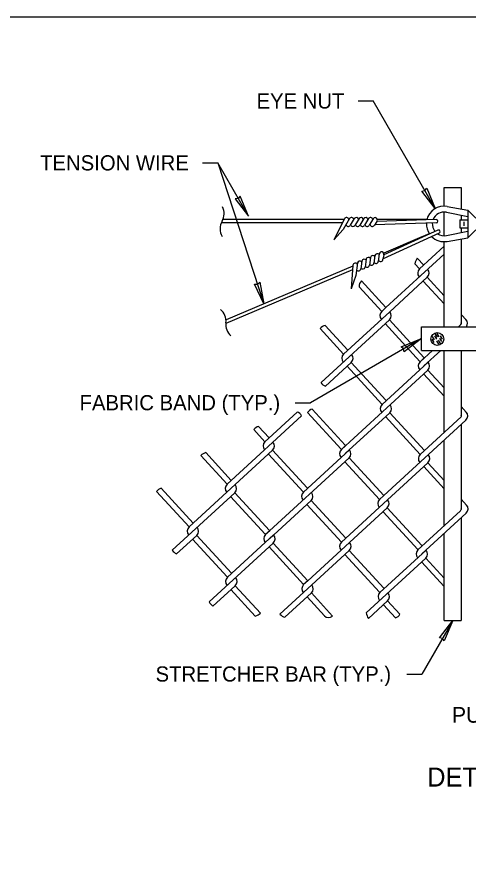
# Model space of a CAD drawing. Extents: x 99862 to 104211, y 98939 to 105076.
# Drawn here: x 101442 to 101919, y 104179 to 105076 of the extents above; entities that cross this region are included whole.
import ezdxf

# ---------------------------------------------------------------- set-up
doc = ezdxf.new("R2010")
doc.units = 0
for name, color, linetype in [('Level 1', 7, 'Continuous'), ('Level 15', 7, 'Continuous'), ('Level 2', 7, 'Continuous'), ('Level 20', 7, 'Continuous'), ('Level 4', 7, 'Continuous'), ('Level 7', 7, 'Continuous')]:
    doc.layers.add(name, color=color, linetype=linetype)

msp = doc.modelspace()

# ---------------------------------------------------------------- linework, layer by layer
at = {"layer": 'Level 1'}
msp.add_lwpolyline([(99862, 102999.5), (103151, 102999.5), (103151, 105075.5), (99862, 105075.5)], close=True, dxfattribs=at)
at = {"layer": 'Level 15'}
for p, q in [((101801.93, 104987.03), (101817.93, 104987.03)), ((101883.35, 104873.71), (101817.93, 104987.03)), ((101637.88, 104921.79), (101653.88, 104921.79)), ((101686.38, 104865.5), (101653.88, 104921.79)), ((101653.88, 104921.79), (101702.72, 104773.36)), ((101868.71, 104736.56), (101751.71, 104669.01)), ((101735.71, 104669.01), (101751.71, 104669.01)), ((101901.78, 104439.37), (101869.28, 104383.07)), ((101853.28, 104383.07), (101869.28, 104383.07))]:
    msp.add_line(p, q, dxfattribs=at)
for points in [[(101883.35, 104873.71), (101869.35, 104891.99), (101872.46, 104892.57), (101874.52, 104894.98)], [(101686.38, 104865.5), (101677.55, 104886.77), (101675.5, 104884.36), (101672.38, 104883.78)], [(101702.72, 104773.36), (101692.75, 104794.11), (101695.91, 104794.04), (101698.42, 104795.98)], [(101868.71, 104736.56), (101850.43, 104722.56), (101849.86, 104725.67), (101847.45, 104727.73)], [(101901.78, 104439.37), (101892.95, 104418.1), (101890.9, 104420.51), (101887.78, 104421.09)]]:
    msp.add_lwpolyline(points, close=True, dxfattribs=at)
at = {"layer": 'Level 2'}
for p, q in [((101896.01, 104875.93), (101917.63, 104872.08)), ((101917.63, 104872.08), (101926.05, 104863.66)), ((101917.63, 104872.08), (101917.63, 104842.88)), ((101787.51, 104862.78), (101776.31, 104840.57)), ((101792.9, 104863.08), (101786.2, 104851.62)), ((101797.96, 104863.17), (101793.76, 104856.09)), ((101802.99, 104863.21), (101798.54, 104855.75)), ((101807.94, 104863.14), (101803.75, 104856.03)), ((101812.87, 104863.05), (101808.75, 104855.96)), ((101817.82, 104862.97), (101813.83, 104856.05)), ((101895.11, 104869.75), (101917.63, 104865.37)), ((101785.33, 104858.47), (101657.69, 104858.47)), ((101787.1, 104861.97), (101659.44, 104861.97)), ((101821.83, 104860.01), (101819.14, 104856.18)), ((101884.43, 104858.52), (101819.39, 104856.53)), ((101884.28, 104861.92), (101821.83, 104860.02)), ((101863.33, 104861.93), (101822.43, 104861.93)), ((101874.51, 104861.93), (101863.33, 104861.93)), ((101909.39, 104861.65), (101909.39, 104853.31)), ((101909.39, 104861.65), (101917.63, 104861.65)), ((101913.55, 104859.56), (101913.55, 104855.4)), ((101786.2, 104851.62), (101776.31, 104840.57)), ((101887.39, 104847.76), (101828.27, 104820.58)), ((101885.93, 104850.83), (101829.16, 104824.75)), ((101877.11, 104847.11), (101866.64, 104842.68)), ((101895.14, 104845.22), (101917.63, 104849.65)), ((101909.39, 104853.31), (101917.63, 104853.31)), ((101917.63, 104842.88), (101926.05, 104851.3)), ((101866.64, 104842.68), (101828.97, 104826.74)), ((101896.01, 104839.03), (101917.63, 104842.88)), ((101805.95, 104818.34), (101804.85, 104810.18)), ((101810.57, 104820.34), (101809.37, 104811.74)), ((101815.15, 104822.21), (101814.06, 104814.03)), ((101819.73, 104824.04), (101818.7, 104815.91)), ((101824.32, 104825.9), (101823.33, 104817.97)), ((101829.17, 104824.74), (101828.18, 104820.17)), ((101796.15, 104809.1), (101662.54, 104752.56)), ((101796.41, 104813.01), (101662.7, 104756.43)), ((101796.47, 104813.91), (101794.82, 104789.09)), ((101801.32, 104816.29), (101799.62, 104803.12)), ((101799.62, 104803.12), (101794.82, 104789.09))]:
    msp.add_line(p, q, dxfattribs=at)
msp.add_circle((101885.54, 104736.08), 6.76, dxfattribs=at)
for centre, radius, start, end in [((101644.72, 104868.22), 15.99, 330, 26.99342), ((101892.72, 104857.48), 18.75, 79.88873, 167.22506), ((101789.74, 104861.65), 2.5, 6.40357, 153.24227), ((101794.95, 104861.65), 2.5, 12.67704, 145.12641), ((101799.95, 104861.65), 2.5, 12.59822, 142.68795), ((101804.95, 104861.65), 2.5, 12.71791, 141.47087), ((101809.95, 104861.65), 2.5, 12.8499, 143.37719), ((101814.95, 104861.65), 2.5, 12.90749, 146.13672), ((101819.95, 104861.65), 2.5, 318.96056, 148.1098), ((101892.72, 104857.48), 12.5, 78.97929, 159.15425), ((101672.42, 104852.23), 15.99, 150, 210), ((101791.6, 104857.36), 2.5, 194.6987, 329.36298), ((101796.58, 104857.31), 2.5, 193.30049, 321.47087), ((101801.58, 104857.31), 2.5, 192.67765, 329.47272), ((101806.65, 104857.31), 2.5, 191.7767, 327.41573), ((101811.65, 104857.31), 2.5, 192.8499, 329.97706), ((101816.91, 104857.31), 2.5, 185.27391, 333.22218), ((101892.72, 104857.48), 18.75, 177.80235, 214.51032), ((101892.72, 104857.48), 12.5, 175.82468, 219.51772), ((101884.43, 104860.22), 1.71, 270, 90), ((101892.72, 104857.48), 12.5, 236.61904, 281.13621), ((101886.73, 104849.33), 1.71, 292.93564, 112.93564), ((101892.72, 104857.48), 18.75, 225.33181, 280.11127), ((101826.79, 104825.51), 2.5, 341.89619, 171.04544), ((101803.77, 104815.77), 2.5, 35.61267, 168.06204), ((101808.37, 104817.72), 2.5, 35.53386, 165.62358), ((101812.98, 104819.67), 2.5, 35.65354, 164.40651), ((101817.58, 104821.62), 2.5, 35.78553, 166.31283), ((101820.84, 104818.28), 2.5, 215.78553, 352.91269), ((101822.18, 104823.57), 2.5, 35.84312, 169.07235), ((101825.68, 104820.33), 2.5, 208.20955, 356.15782), ((101798.97, 104813.74), 2.5, 29.3392, 176.17791), ((101802.36, 104810.52), 2.5, 217.63433, 352.29861), ((101806.96, 104812.41), 2.5, 216.23612, 344.40651), ((101811.57, 104814.36), 2.5, 215.61329, 352.40835), ((101816.23, 104816.33), 2.5, 214.71234, 350.35137), ((101647.39, 104755.2), 15.35, 352.34425, 52.34425), ((101677.83, 104751.11), 15.35, 172.34425, 229.33767)]:
    msp.add_arc(centre, radius, start, end, dxfattribs=at)
at = {"layer": 'Level 4'}
for p, q in [((101892.69, 104833.83), (101866.77, 104810.04)), ((101892.69, 104825.69), (101831.28, 104769.32)), ((101864.41, 104821.48), (101871.19, 104814.09)), ((101861.87, 104815.36), (101866.77, 104810.04)), ((101874.88, 104801.2), (101835.34, 104764.9)), ((101866.4, 104801.56), (101866.4, 104801.56)), ((101874.88, 104801.2), (101892.69, 104781.79)), ((101803.01, 104791.25), (101826.86, 104765.26)), ((101805.61, 104797.29), (101831.28, 104769.32)), ((101870.46, 104797.14), (101892.69, 104773.06)), ((101835.34, 104764.9), (101786.72, 104720.27)), ((101831.28, 104769.32), (101826.86, 104765.26)), ((101834.98, 104756.42), (101762.86, 104690.22)), ((101826.5, 104756.78), (101826.5, 104756.78)), ((101834.98, 104756.42), (101871.49, 104716.64)), ((101910.87, 104761.98), (101911.4, 104761.41)), ((101911.4, 104761.41), (101915.79, 104756.63)), ((101761.92, 104747.29), (101786.72, 104720.27)), ((101767.21, 104750.39), (101791.14, 104724.32)), ((101830.56, 104752.36), (101867.07, 104712.58)), ((101910.5, 104751.55), (101907.81, 104749.09)), ((101880.34, 104724.02), (101867.41, 104712.21)), ((101889.14, 104724.02), (101871.47, 104707.79)), ((101794.83, 104711.43), (101767.49, 104686.33)), ((101786.35, 104711.79), (101786.35, 104711.79)), ((101794.83, 104711.43), (101831.35, 104671.64)), ((101875.89, 104711.85), (101827.27, 104667.22)), ((101867.07, 104712.58), (101867.41, 104712.21)), ((101871.83, 104716.27), (101867.41, 104712.21)), ((101871.49, 104716.64), (101871.83, 104716.27)), ((101875.52, 104703.37), (101784.41, 104619.74)), ((101790.41, 104707.37), (101826.93, 104667.59)), ((101867.05, 104703.74), (101867.05, 104703.74)), ((101875.52, 104703.37), (101892.69, 104684.67)), ((101871.1, 104699.32), (101892.69, 104675.8)), ((101826.93, 104667.59), (101827.27, 104667.22)), ((101831.35, 104671.64), (101831.69, 104671.28)), ((101737.74, 104659.02), (101703.72, 104627.79)), ((101748.72, 104658.62), (101784.07, 104620.11)), ((101753.44, 104662.36), (101788.5, 104624.17)), ((101835.38, 104658.38), (101788.47, 104615.32)), ((101826.9, 104658.74), (101826.9, 104658.74)), ((101835.38, 104658.38), (101871.9, 104618.6)), ((101910.87, 104664.86), (101916.1, 104659.17)), ((101742.38, 104655.13), (101668.23, 104587.08)), ((101915.74, 104650.69), (101829.04, 104571.12)), ((101830.96, 104654.32), (101867.48, 104614.54)), ((101910.57, 104654.1), (101867.48, 104614.54)), ((101907.26, 104651.06), (101907.26, 104651.06)), ((101691.96, 104640.61), (101703.72, 104627.79)), ((101696.97, 104644.02), (101708.14, 104631.85)), ((101788.83, 104623.8), (101784.41, 104619.74)), ((101788.5, 104624.17), (101788.83, 104623.8)), ((101636.02, 104613.3), (101663.81, 104583.02)), ((101641.35, 104616.37), (101668.23, 104587.08)), ((101711.83, 104618.95), (101672.29, 104582.66)), ((101703.36, 104619.32), (101703.36, 104619.32)), ((101707.41, 104614.9), (101743.93, 104575.11)), ((101711.83, 104618.95), (101748.35, 104579.17)), ((101792.89, 104619.38), (101744.27, 104574.75)), ((101784.07, 104620.11), (101784.41, 104619.74)), ((101792.53, 104610.9), (101704.36, 104529.97)), ((101784.05, 104611.26), (101784.05, 104611.26)), ((101788.11, 104606.84), (101824.62, 104567.06)), ((101792.53, 104610.9), (101829.04, 104571.12)), ((101875.59, 104605.7), (101833.1, 104566.7)), ((101867.11, 104606.06), (101867.11, 104606.06)), ((101875.59, 104605.7), (101892.69, 104587.07)), ((101871.17, 104601.64), (101892.69, 104578.2)), ((101668.23, 104587.08), (101663.81, 104583.02)), ((101589.23, 104575.54), (101623.67, 104538.02)), ((101594.19, 104579.02), (101628.09, 104542.08)), ((101672.29, 104582.66), (101623.67, 104538.02)), ((101748.35, 104579.17), (101748.69, 104578.8)), ((101671.93, 104574.18), (101605.78, 104513.46)), ((101663.45, 104574.54), (101663.45, 104574.54)), ((101667.51, 104570.12), (101704.02, 104530.34)), ((101671.93, 104574.18), (101708.45, 104534.4)), ((101743.93, 104575.11), (101744.27, 104574.75)), ((101833.1, 104566.7), (101784.48, 104522.07)), ((101829.04, 104571.12), (101824.62, 104567.06)), ((101910.87, 104567.26), (101916.5, 104561.13)), ((101752.38, 104565.91), (101708.42, 104525.55)), ((101743.91, 104566.27), (101743.91, 104566.27)), ((101747.96, 104561.85), (101784.48, 104522.07)), ((101832.74, 104558.22), (101748.99, 104481.35)), ((101752.38, 104565.91), (101788.9, 104526.12)), ((101824.26, 104558.58), (101824.26, 104558.58)), ((101832.74, 104558.22), (101869.25, 104518.44)), ((101828.32, 104554.16), (101864.83, 104514.38)), ((101910, 104555.04), (101865.17, 104514.01)), ((101916.14, 104552.65), (101869.23, 104509.59)), ((101907.66, 104553.02), (101907.66, 104553.02)), ((101708.78, 104534.03), (101704.36, 104529.97)), ((101708.45, 104534.4), (101708.78, 104534.03)), ((101631.78, 104529.18), (101610.54, 104509.68)), ((101623.31, 104529.55), (101623.31, 104529.55)), ((101627.36, 104525.13), (101663.88, 104485.35)), ((101631.78, 104529.18), (101668.3, 104489.4)), ((101712.84, 104529.61), (101664.22, 104484.98)), ((101704.02, 104530.34), (101704.36, 104529.97)), ((101712.48, 104521.13), (101644.89, 104459.09)), ((101704, 104521.49), (101704, 104521.49)), ((101708.06, 104517.07), (101744.57, 104477.29)), ((101712.48, 104521.13), (101748.99, 104481.35)), ((101792.59, 104513.23), (101753.05, 104476.93)), ((101784.12, 104513.59), (101784.12, 104513.59)), ((101792.59, 104513.23), (101829.11, 104473.44)), ((101873.65, 104513.65), (101825.03, 104469.02)), ((101864.83, 104514.38), (101865.17, 104514.01)), ((101869.59, 104518.07), (101865.17, 104514.01)), ((101869.25, 104518.44), (101869.59, 104518.07)), ((101788.17, 104509.17), (101824.69, 104469.39)), ((101873.29, 104505.17), (101810.67, 104447.7)), ((101864.81, 104505.54), (101864.81, 104505.54)), ((101873.29, 104505.17), (101892.69, 104484.04)), ((101868.87, 104501.12), (101892.69, 104475.16)), ((101668.3, 104489.4), (101668.64, 104489.03)), ((101663.88, 104485.35), (101664.22, 104484.98)), ((101753.05, 104476.93), (101719.57, 104446.2)), ((101748.99, 104481.35), (101744.57, 104477.29)), ((101672.33, 104476.14), (101648.88, 104454.61)), ((101663.86, 104476.5), (101663.86, 104476.5)), ((101667.91, 104472.08), (101693.54, 104444.16)), ((101672.33, 104476.14), (101699.01, 104447.08)), ((101752.69, 104468.45), (101724.77, 104442.82)), ((101744.21, 104468.81), (101744.21, 104468.81)), ((101752.69, 104468.45), (101775, 104444.14)), ((101824.69, 104469.39), (101825.03, 104469.02)), ((101829.11, 104473.44), (101829.45, 104473.08)), ((101748.27, 104464.39), (101766.53, 104444.5)), ((101833.14, 104460.18), (101812.96, 104441.65)), ((101824.67, 104460.54), (101824.67, 104460.54)), ((101833.14, 104460.18), (101846.07, 104446.1)), ((101828.72, 104456.12), (101841.36, 104442.36))]:
    msp.add_line(p, q, dxfattribs=at)
for centre, radius, start, end in [((101881.62, 104810.77), 20.28, 148.11065, 166.89404), ((101870.82, 104805.62), 6, 132.54951, 222.54951), ((101870.82, 104805.62), 6, 312.54951, 42.54951), ((101810.9, 104791.43), 7.9, 132.12475, 181.32258), ((101830.92, 104760.84), 6, 132.54951, 222.54951), ((101830.92, 104760.84), 6, 312.54951, 42.54951), ((101911.37, 104752.57), 6, 324.62115, 42.54951), ((101770.03, 104739.5), 11.25, 104.49444, 136.16864), ((101909.48, 104752.66), 1.5, 312.54951, 22.14955), ((101790.77, 104715.85), 6, 132.54951, 222.54951), ((101790.77, 104715.85), 6, 312.54951, 42.54951), ((101871.47, 104707.79), 6, 132.54951, 222.54951), ((101871.47, 104707.79), 6, 312.54951, 42.54951), ((101771.01, 104695.22), 9.57, 211.53342, 248.40821), ((101831.32, 104662.8), 6, 132.54951, 222.54951), ((101831.32, 104662.8), 6, 312.54951, 42.54951), ((101736.96, 104653.37), 5.7, 18.01358, 82.126), ((101756.71, 104653.37), 9.57, 110.02419, 146.68089), ((101911.68, 104655.11), 6, 312.54951, 42.54951), ((101909.56, 104655.2), 1.5, 312.54951, 28.72672), ((101700.56, 104633.36), 11.25, 108.61233, 139.88674), ((101707.78, 104623.37), 6, 132.54951, 222.54951), ((101707.78, 104623.37), 6, 312.54951, 42.54951), ((101645.56, 104602.91), 14.1, 107.36913, 132.54951), ((101788.47, 104615.32), 6, 132.54951, 222.54951), ((101788.47, 104615.32), 6, 312.54951, 42.54951), ((101871.53, 104610.12), 6, 132.54951, 222.54951), ((101871.53, 104610.12), 6, 312.54951, 42.54951), ((101599.62, 104566), 14.1, 112.6696, 137.44966), ((101667.87, 104578.6), 6, 132.54951, 222.54951), ((101667.87, 104578.6), 6, 312.54951, 42.54951), ((101748.33, 104570.33), 6, 132.54951, 222.54951), ((101748.33, 104570.33), 6, 312.54951, 42.54951), ((101828.68, 104562.64), 6, 132.54951, 222.54951), ((101828.68, 104562.64), 6, 312.54951, 42.54951), ((101907.97, 104557.25), 3, 312.54951, 14.55865), ((101912.08, 104557.07), 6, 312.54951, 42.54951), ((101627.73, 104533.6), 6, 132.54951, 222.54951), ((101627.73, 104533.6), 6, 312.54951, 42.54951), ((101708.42, 104525.55), 6, 132.54951, 222.54951), ((101708.42, 104525.55), 6, 312.54951, 42.54951), ((101788.54, 104517.65), 6, 132.54951, 222.54951), ((101788.54, 104517.65), 6, 312.54951, 42.54951), ((101616.71, 104522.33), 14.07, 219.07533, 244.00701), ((101869.23, 104509.59), 6, 132.54951, 222.54951), ((101869.23, 104509.59), 6, 312.54951, 42.54951), ((101668.28, 104480.56), 6, 132.54951, 222.54951), ((101668.28, 104480.56), 6, 312.54951, 42.54951), ((101748.63, 104472.87), 6, 132.54951, 222.54951), ((101748.63, 104472.87), 6, 312.54951, 42.54951), ((101829.09, 104464.6), 6, 132.54951, 222.54951), ((101829.09, 104464.6), 6, 312.54951, 42.54951), ((101660.9, 104469.3), 18.98, 212.52003, 230.70818), ((101690.59, 104456.25), 12.44, 283.72177, 312.54951), ((101728.74, 104454.61), 12.44, 222.54951, 251.37724), ((101770.95, 104448.56), 6, 222.54951, 312.54951), ((101822.08, 104448.56), 11.44, 184.33863, 217.15545), ((101840.27, 104448.56), 6.3, 279.91518, 336.96718)]:
    msp.add_arc(centre, radius, start, end, dxfattribs=at)
at = {"layer": 'Level 7'}
for p, q in [((101892.69, 104876.23), (101892.69, 104895.93)), ((101892.69, 104895.93), (101910.87, 104895.93)), ((101892.69, 104844.98), (101892.69, 104869.98)), ((101892.69, 104749.09), (101892.69, 104838.73)), ((101868.71, 104724.02), (101868.71, 104749.09)), ((101868.71, 104749.09), (102006.64, 104749.09)), ((101882.72, 104735.27), (101880.52, 104738.66)), ((101885.08, 104736), (101882.88, 104739.39)), ((101885.79, 104738.1), (101883.59, 104741.49)), ((101887.39, 104738.47), (101885.23, 104741.8)), ((101890.96, 104736.02), (101888.76, 104739.4)), ((101882.23, 104732.44), (101880.03, 104735.84)), ((101887.28, 104730.84), (101885.07, 104734.23)), ((101888.97, 104731.49), (101886.8, 104734.85)), ((101890.34, 104733.54), (101888.14, 104736.94)), ((101868.71, 104724.02), (101874.98, 104724.02)), ((101874.98, 104724.02), (101911.95, 104724.02)), ((101892.69, 104637.68), (101892.69, 104724.02)), ((101910.12, 104724.02), (102006.64, 104724.02)), ((101892.69, 104539.27), (101892.69, 104629.54)), ((101892.69, 104439.37), (101892.69, 104531.13)), ((101892.69, 104439.37), (101910.87, 104439.37))]:
    msp.add_line(p, q, dxfattribs=at)
for points in [[(101910.87, 104895.93), (101910.87, 104895.93), (101910.87, 104873.28)], [(101910.87, 104866.68), (101910.87, 104861.65)], [(101910.87, 104853.31), (101910.87, 104848.32)], [(101910.87, 104841.68), (101910.87, 104810.73)], [(101910.87, 104810.73), (101910.87, 104752.09)], [(101910.87, 104724.02), (101910.87, 104654.48)], [(101910.87, 104646.23), (101910.87, 104556.5)], [(101910.87, 104547.82), (101910.87, 104439.37)]]:
    msp.add_lwpolyline(points, dxfattribs=at)

# ---------------------------------------------------------------- texts
at = {"layer": 'Level 20'}
for s, height, p in [('EYE NUT', 16, (101694.84, 104979.03)), ('TENSION WIRE', 16, (101466.53, 104913.8)), ('STRETCHER BAR (TYP.)', 16, (101588.35, 104375.08)), ('PULL POST', 16.5, (101901.1, 104331.77)), ('DETAIL', 20, (101874.88, 104264.44))]:
    msp.add_text(s, height=height, dxfattribs=at).set_placement(p)
msp.add_text('FABRIC BAND (TYP.)', height=16, rotation=360, dxfattribs=at).set_placement((101508.21, 104661.01))

doc.saveas('drawing.dxf')
